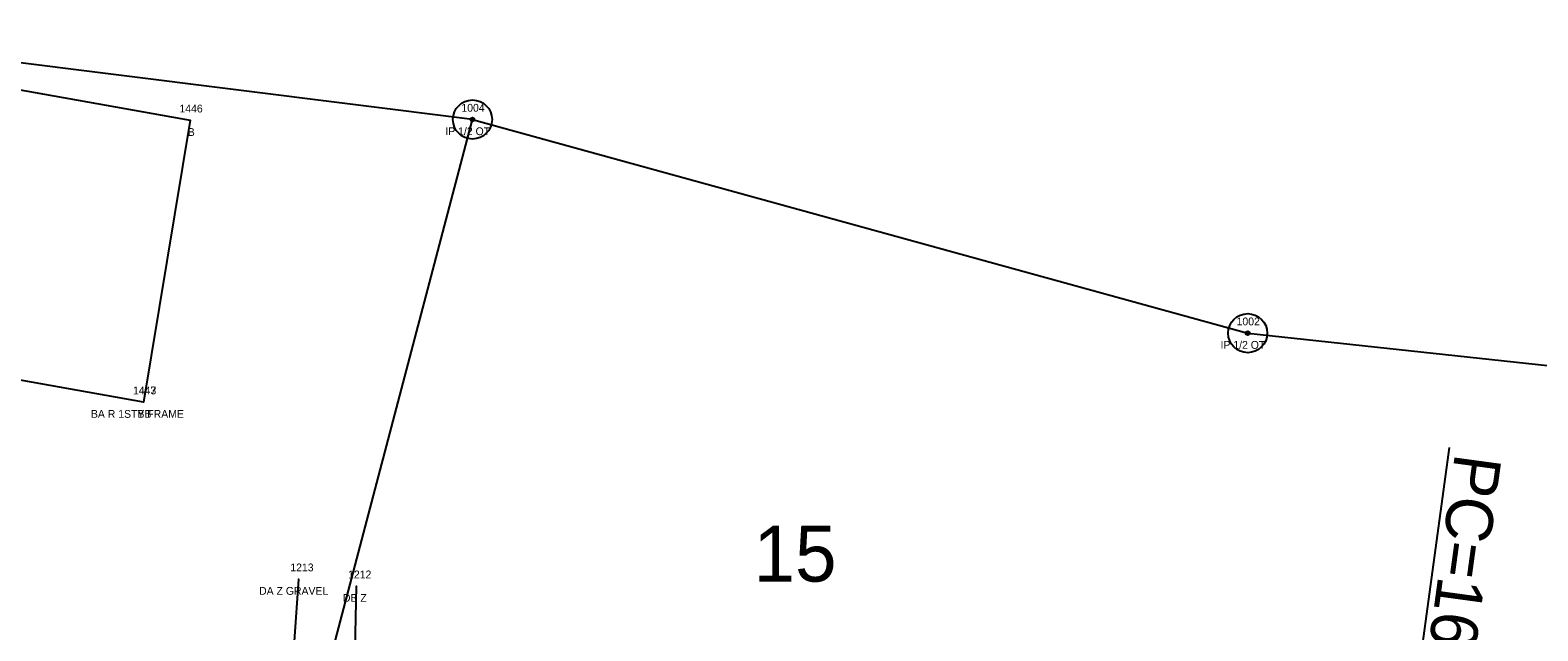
# Model space of a CAD drawing. Extents: x 1812113 to 1819860, y 1177395 to 1181185.
# Drawn here: x 1813371.7 to 1813564.5, y 1178857.4 to 1178934.2 of the extents above; entities that cross this region are included whole.
import ezdxf

# ---------------------------------------------------------------- set-up
doc = ezdxf.new("R2010")
doc.units = 0
for name, color, linetype in [('RD_EX_Bldg', 7, 'Continuous'), ('RD_EX_Bldg_txCode', 7, 'Continuous'), ('RD_EX_Driveway', 7, 'Continuous'), ('RD_EX_Driveway_txCode', 7, 'Continuous'), ('RD_EX_DV_Prop', 7, 'Continuous'), ('RD_EX_DV_Prop_txCode', 7, 'Continuous'), ('RD_EX_DV_PropPin', 7, 'Continuous'), ('RD_EX_DV_TX_Prop', 7, 'Continuous'), ('RD_HC_CL', 7, 'Continuous'), ('RD_HC_Data', 7, 'Continuous'), ('RD_SMD_Locator', 7, 'Continuous')]:
    doc.layers.add(name, color=color, linetype=linetype)

msp = doc.modelspace()

# ---------------------------------------------------------------- linework, layer by layer
at = {"layer": 'RD_EX_Bldg'}
msp.add_lwpolyline([(1813386.16, 1178886.63), (1813354.34, 1178892.31), (1813360.31, 1178928.37), (1813392.12, 1178922.69), (1813386.16, 1178886.63)], dxfattribs=at)
at = {"layer": 'RD_EX_Driveway'}
for p, q in [((1813405.99, 1178863.99), (1813402.78, 1178818.92)), ((1813412.51, 1178818.62), (1813413.38, 1178863.09))]:
    msp.add_line(p, q, dxfattribs=at)
at = {"layer": 'RD_EX_DV_Prop'}
for p, q in [((1813428.23, 1178922.79), (1813336.92, 1178934.22)), ((1813400.47, 1178817.38), (1813428.23, 1178922.79)), ((1813428.23, 1178922.79), (1813527.37, 1178895.46)), ((1813527.37, 1178895.46), (1813637.89, 1178883.55))]:
    msp.add_line(p, q, dxfattribs=at)
at = {"layer": 'RD_EX_DV_PropPin'}
for centre, radius in [((1813428.23, 1178922.79), 2.5), ((1813428.23, 1178922.79), 0.25), ((1813527.37, 1178895.46), 2.5), ((1813527.37, 1178895.46), 0.25)]:
    msp.add_circle(centre, radius, dxfattribs=at)
at = {"layer": 'RD_HC_CL'}
msp.add_arc((1813766.93, 1180445.18), 1689.31, 243.58271, 262.2191, dxfattribs=at)
at = {"layer": 'RD_HC_Data'}
msp.add_line((1813538.22, 1178771.42), (1813553.17, 1178880.85), dxfattribs=at)
at = {"layer": 'RD_SMD_Locator'}
for centre in [(1813392.12, 1178922.69), (1813386.16, 1178886.63), (1813386.16, 1178886.63), (1813405.99, 1178863.99), (1813413.38, 1178863.09)]:
    msp.add_circle(centre, 0.001, dxfattribs=at)

# ---------------------------------------------------------------- texts
at = {"layer": 'RD_EX_Bldg_txCode'}
for s, p in [('1446', (1813390.75, 1178923.69)), ('B', (1813391.82, 1178920.69)), ('1443', (1813384.81, 1178887.63)), ('1447', (1813384.81, 1178887.63)), ('BA R 1STY FRAME', (1813379.43, 1178884.63)), ('BB', (1813385.38, 1178884.63))]:
    msp.add_text(s, height=1, dxfattribs=at).set_placement(p)
at = {"layer": 'RD_EX_Driveway_txCode'}
for s, p in [('1213', (1813404.93, 1178864.99)), ('1212', (1813412.32, 1178864.09)), ('DA Z GRAVEL', (1813400.94, 1178861.99)), ('DB Z', (1813411.66, 1178861.09))]:
    msp.add_text(s, height=1, dxfattribs=at).set_placement(p)
at = {"layer": 'RD_EX_DV_Prop_txCode'}
for s, p in [('1004', (1813426.81, 1178923.79)), ('IP 1/2 OT', (1813424.76, 1178920.79)), ('1002', (1813525.95, 1178896.46)), ('IP 1/2 OT', (1813523.9, 1178893.46))]:
    msp.add_text(s, height=1, dxfattribs=at).set_placement(p)
at = {"layer": 'RD_EX_DV_TX_Prop'}
msp.add_text('15', height=7.14, dxfattribs=at).set_placement((1813464.17, 1178863.68))
at = {"layer": 'RD_HC_Data'}
msp.add_text('PC=16+53.08', height=6, rotation=262.2191, dxfattribs=at).set_placement((1813553.9, 1178880.21))

doc.saveas('drawing.dxf')
